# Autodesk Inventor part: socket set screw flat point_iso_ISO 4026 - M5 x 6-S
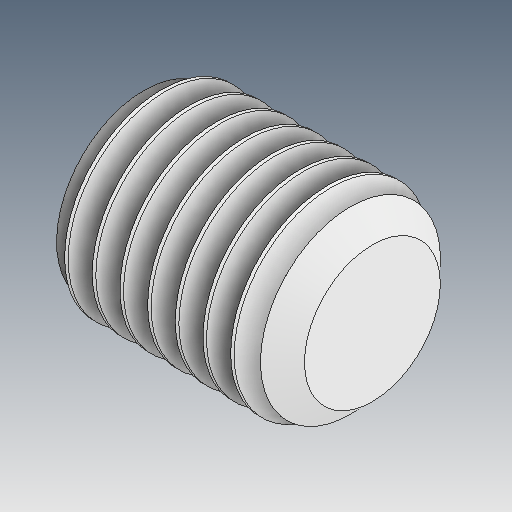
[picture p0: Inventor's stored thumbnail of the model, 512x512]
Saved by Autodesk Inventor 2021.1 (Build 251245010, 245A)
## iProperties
Created: 2021-05
Part Number: socket set screw flat point_iso_ISO 4026 - M5 x 6-S
Material: Ogólny
Document SubType Name: Modeling
Designer: user
Density: 1 g/cm^3
Appearance: Domyślna
Author: user
Revision Number: ÈÎºÎ
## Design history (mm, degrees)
feature "ÊäÈë1"
node "Bryła1"
